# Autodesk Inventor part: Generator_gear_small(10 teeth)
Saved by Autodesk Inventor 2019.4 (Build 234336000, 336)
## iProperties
Created: 2020-04
Part Number: Generator_gear_small(10 teeth)
Material: Generic
Description: Spur Gear; Module: 0.900000; Num Teeth: 10; Pressure Angle: 20.000000; Backlash: 0.00 mm
Document SubType Name: Modeling
Designer: Administrator
Density: 1 g/cm^3
Appearance: Default
Title: Generator_gear_small(10 teeth) v3
Author: Administrator
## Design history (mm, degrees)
feature "Body1"
body "Solid1"
